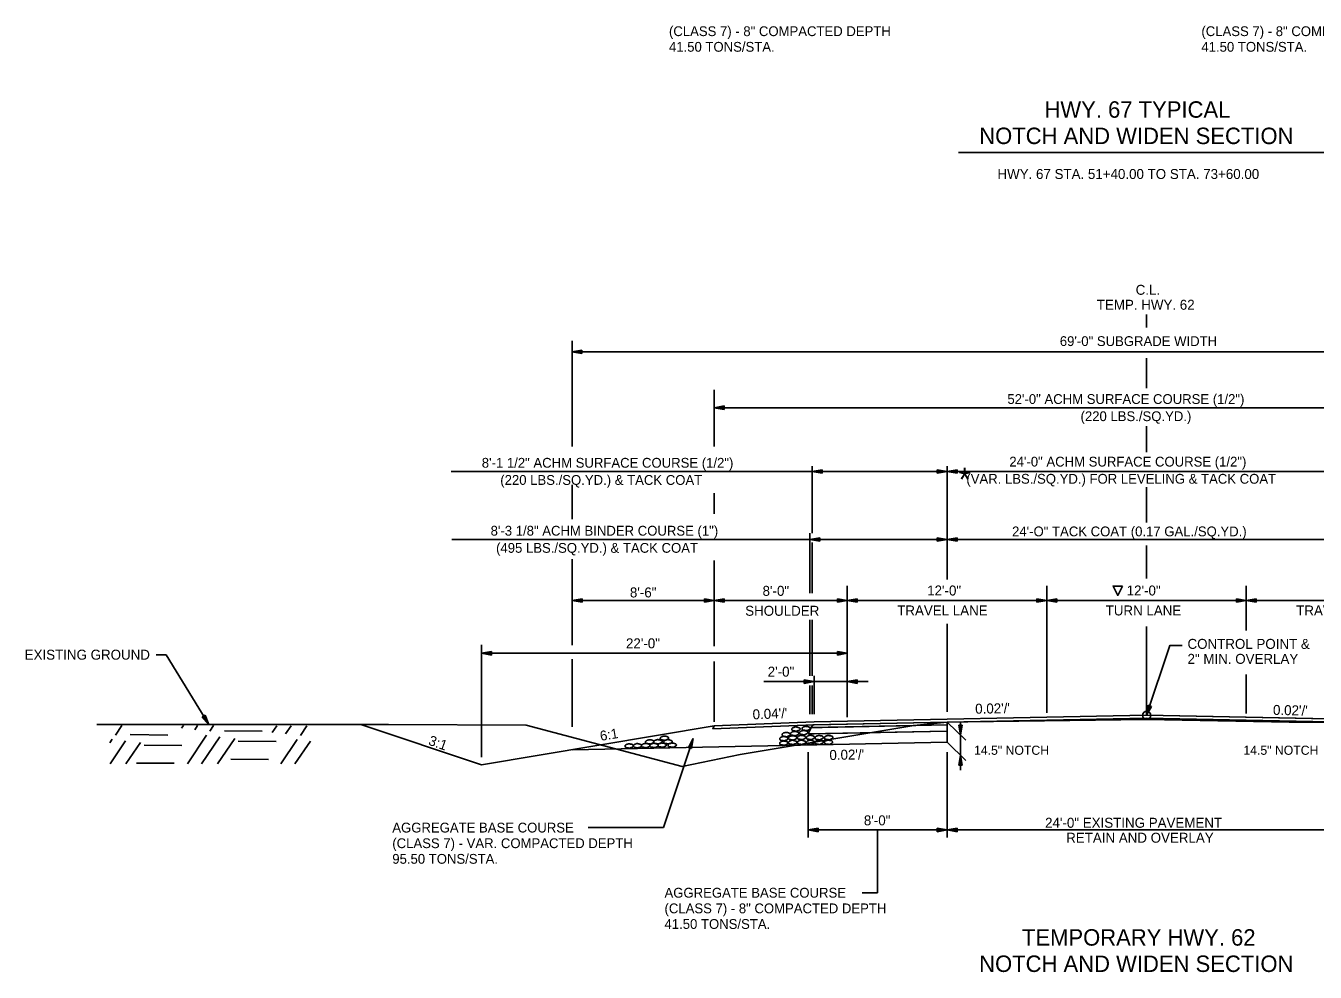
# Model space of a CAD drawing. Extents: x 1734743 to 1735935, y 759845 to 763831.
# Drawn here: x 1735682.6 to 1735760.2, y 762323.5 to 762380.5 of the extents above; entities that cross this region are included whole.
import ezdxf

# ---------------------------------------------------------------- set-up
doc = ezdxf.new("R2010")
doc.units = 0
for name, color, linetype in [('1', 7, 'Continuous'), ('10', 7, 'Continuous'), ('19', 7, 'Continuous'), ('20', 7, 'Continuous'), ('42', 7, 'Continuous'), ('Level 1', 7, 'Continuous'), ('R_Draft', 7, 'Continuous'), ('R_Prop Surface', 7, 'Continuous')]:
    doc.layers.add(name, color=color, linetype=linetype)

# ---------------------------------------------------------------- blocks, each defined once
blk = doc.blocks.new('ROCKS')
at = {"layer": '1'}
blk.add_spline([(0.013, 0.06), (0.053, 0.053), (0.107, 0.033), (0.133, 0.013), (0.133, -0.007), (0.12, -0.033), (0.107, -0.04), (0.073, -0.053), (0.033, -0.067), (0.013, -0.067), (-0.02, -0.06), (-0.06, -0.053), (-0.087, -0.047), (-0.113, -0.02), (-0.113, -0.007), (-0.107, 0.02), (-0.087, 0.033), (-0.067, 0.047), (-0.033, 0.053), (-0.02, 0.06), (0.013, 0.06)], degree=3, dxfattribs=at)

msp = doc.modelspace()

# ---------------------------------------------------------------- linework, layer by layer
at = {"layer": '1'}
msp.add_line((1735738.718, 762372.859), (1735761.293, 762372.859), dxfattribs=at)
at = {"layer": '10'}
msp.add_lwpolyline([(1735748.579, 762346.77), (1735748.298, 762346.208), (1735748.017, 762346.77)], close=True, dxfattribs=at)
at = {"layer": '19'}
for p, q in [((1735750.035, 762362.323), (1735750.035, 762363.109)), ((1735750.035, 762358.676), (1735750.035, 762360.487)), ((1735750.035, 762354.815), (1735750.035, 762356.383)), ((1735750.035, 762350.598), (1735750.035, 762352.723)), ((1735750.035, 762347.228), (1735750.035, 762349.204)), ((1735750.035, 762338.99), (1735750.035, 762344.343)), ((1735710.635, 762342.827), (1735710.035, 762342.722)), ((1735710.035, 762342.722), (1735732.035, 762342.722)), ((1735710.035, 762342.722), (1735710.635, 762342.617)), ((1735710.635, 762342.772), (1735710.195, 762342.737)), ((1735710.195, 762342.707), (1735710.635, 762342.667)), ((1735710.635, 762342.617), (1735710.635, 762342.827)), ((1735731.435, 762342.827), (1735731.435, 762342.617)), ((1735732.035, 762342.722), (1735731.435, 762342.827)), ((1735731.875, 762342.737), (1735731.435, 762342.772)), ((1735731.435, 762342.617), (1735732.035, 762342.722)), ((1735731.435, 762342.667), (1735731.875, 762342.707)), ((1735727.006, 762341.016), (1735730.035, 762341.016)), ((1735729.435, 762341.121), (1735729.435, 762340.911)), ((1735730.035, 762341.016), (1735729.435, 762341.121)), ((1735729.875, 762341.031), (1735729.435, 762341.066)), ((1735729.435, 762340.911), (1735730.035, 762341.016)), ((1735729.435, 762340.961), (1735729.875, 762341.001)), ((1735750.035, 762338.99), (1735750.127, 762339.592)), ((1735750.127, 762339.592), (1735750.325, 762339.525)), ((1735750.035, 762338.99), (1735730.035, 762338.59)), ((1735750.035, 762338.824), (1735730.035, 762338.424)), ((1735750.325, 762339.525), (1735750.035, 762338.99)), ((1735750.035, 762338.99), (1735770.04, 762338.59)), ((1735750.035, 762338.824), (1735770.04, 762338.424)), ((1735750.076, 762339.144), (1735750.176, 762339.571)), ((1735750.28, 762339.537), (1735750.1, 762339.138)), ((1735688.008, 762337.793), (1735688.401, 762338.375)), ((1735691.994, 762338.218), (1735692.101, 762338.368)), ((1735692.789, 762338.124), (1735692.955, 762338.368)), ((1735693.684, 762338.03), (1735693.911, 762338.368)), ((1735694.572, 762338.057), (1735696.832, 762338.04)), ((1735697.448, 762337.966), (1735697.711, 762338.36)), ((1735698.242, 762337.872), (1735698.575, 762338.36)), ((1735699.138, 762337.778), (1735699.52, 762338.351)), ((1735710.035, 762336.017), (1735702.77, 762338.439)), ((1735730.035, 762338.424), (1735723.95, 762338.18)), ((1735724.035, 762338.35), (1735723.95, 762338.18)), ((1735730.035, 762338.59), (1735724.035, 762338.35)), ((1735729.867, 762338.254), (1735729.677, 762337.875)), ((1735729.867, 762338.254), (1735729.677, 762337.875)), ((1735738.035, 762338.042), (1735729.677, 762337.875)), ((1735729.95, 762338.42), (1735729.867, 762338.254)), ((1735738.035, 762338.417), (1735729.867, 762338.254)), ((1735738.035, 762338.042), (1735738.034, 762338.416)), ((1735738.034, 762338.416), (1735738.034, 762338.416)), ((1735738.035, 762338.584), (1735738.035, 762337.375)), ((1735738.035, 762338.042), (1735738.035, 762338.042)), ((1735738.741, 762338.39), (1735738.951, 762338.39)), ((1735738.846, 762337.79), (1735738.741, 762338.39)), ((1735738.831, 762337.95), (1735738.791, 762338.39)), ((1735738.951, 762338.39), (1735738.846, 762337.79)), ((1735738.896, 762338.39), (1735738.861, 762337.95)), ((1735687.667, 762337.326), (1735687.822, 762337.551)), ((1735687.687, 762336.077), (1735688.616, 762337.458)), ((1735688.642, 762336.077), (1735689.511, 762337.363)), ((1735688.897, 762337.83), (1735691.156, 762337.803)), ((1735692.341, 762336.07), (1735693.498, 762337.788)), ((1735693.196, 762336.07), (1735694.292, 762337.695)), ((1735694.151, 762336.07), (1735695.187, 762337.6)), ((1735695.4, 762337.427), (1735697.671, 762337.409)), ((1735697.951, 762336.062), (1735698.951, 762337.536)), ((1735698.806, 762336.063), (1735699.746, 762337.442)), ((1735738.035, 762337.375), (1735715.478, 762336.924)), ((1735720.975, 762332.238), (1735722.76, 762337.598)), ((1735722.76, 762337.598), (1735722.472, 762337.062)), ((1735722.699, 762337.451), (1735722.523, 762337.048)), ((1735722.623, 762337.013), (1735722.725, 762337.442)), ((1735722.67, 762336.997), (1735722.76, 762337.598)), ((1735689.735, 762337.199), (1735691.995, 762337.172)), ((1735722.472, 762337.062), (1735722.67, 762336.997)), ((1735738.741, 762335.982), (1735738.846, 762336.582)), ((1735738.846, 762336.582), (1735738.951, 762335.982)), ((1735689.28, 762336.121), (1735691.55, 762336.103)), ((1735694.956, 762336.358), (1735697.215, 762336.331)), ((1735738.951, 762335.982), (1735738.741, 762335.982)), ((1735738.796, 762335.982), (1735738.831, 762336.422)), ((1735738.861, 762336.422), (1735738.901, 762335.982)), ((1735716.44, 762332.238), (1735720.975, 762332.238)), ((1735733.856, 762328.319), (1735733.856, 762332.092)), ((1735732.928, 762328.319), (1735733.856, 762328.319))]:
    msp.add_line(p, q, dxfattribs=at)
for points in [[(1735752.183, 762343.189), (1735751.428, 762343.189), (1735750.035, 762338.99)], [(1735729.677, 762337.875), (1735730.038, 762337.882), (1735738.035, 762338.042)], [(1735738.034, 762338.416), (1735730.519, 762338.267), (1735729.867, 762338.254)]]:
    msp.add_lwpolyline(points, dxfattribs=at)
for points in [[(1735770.04, 762338.59), (1735750.035, 762338.99), (1735730.035, 762338.59), (1735724.035, 762338.35), (1735723.95, 762338.18), (1735730.035, 762338.424), (1735750.035, 762338.824), (1735770.04, 762338.424), (1735776.12, 762338.18), (1735776.12, 762338.18), (1735776.035, 762338.351), (1735776.035, 762338.351)], [(1735729.95, 762338.42), (1735729.867, 762338.254), (1735738.035, 762338.417), (1735738.035, 762338.417), (1735738.035, 762338.584), (1735738.035, 762338.584)]]:
    msp.add_lwpolyline(points, close=True, dxfattribs=at)
msp.add_circle((1735750.04, 762338.988), 0.25, dxfattribs=at)
at = {"layer": '20'}
for p, q in [((1735715.478, 762361.52), (1735715.478, 762355.162)), ((1735716.073, 762360.963), (1735715.473, 762360.858)), ((1735715.473, 762360.858), (1735716.073, 762360.753)), ((1735715.478, 762360.859), (1735784.593, 762360.859)), ((1735716.073, 762360.908), (1735715.633, 762360.873)), ((1735715.633, 762360.843), (1735716.073, 762360.803)), ((1735716.073, 762360.753), (1735716.073, 762360.963)), ((1735724.035, 762355.162), (1735724.035, 762358.578)), ((1735724.63, 762357.603), (1735724.03, 762357.499)), ((1735724.03, 762357.499), (1735724.63, 762357.393)), ((1735724.035, 762357.498), (1735776.035, 762357.498)), ((1735724.63, 762357.548), (1735724.19, 762357.514)), ((1735724.19, 762357.484), (1735724.63, 762357.443)), ((1735724.63, 762357.393), (1735724.63, 762357.603)), ((1735708.21, 762353.663), (1735729.917, 762353.663)), ((1735729.917, 762349.94), (1735729.917, 762353.981)), ((1735730.517, 762353.768), (1735729.917, 762353.663)), ((1735729.917, 762353.663), (1735738.044, 762353.663)), ((1735729.917, 762353.663), (1735730.517, 762353.558)), ((1735729.917, 762353.663), (1735750.035, 762353.663)), ((1735730.517, 762353.713), (1735730.077, 762353.678)), ((1735730.077, 762353.648), (1735730.517, 762353.608)), ((1735730.517, 762353.558), (1735730.517, 762353.768)), ((1735737.442, 762353.768), (1735737.442, 762353.558)), ((1735738.042, 762353.663), (1735737.442, 762353.768)), ((1735737.882, 762353.678), (1735737.442, 762353.713)), ((1735737.442, 762353.558), (1735738.042, 762353.663)), ((1735737.442, 762353.608), (1735737.882, 762353.648)), ((1735738.042, 762347.154), (1735738.042, 762353.981)), ((1735738.042, 762353.663), (1735738.642, 762353.768)), ((1735738.642, 762353.558), (1735738.042, 762353.663)), ((1735738.202, 762353.678), (1735738.642, 762353.713)), ((1735738.642, 762353.608), (1735738.202, 762353.648)), ((1735738.642, 762353.768), (1735738.642, 762353.558)), ((1735770.153, 762353.663), (1735750.035, 762353.663)), ((1735715.478, 762352.855), (1735715.478, 762350.792)), ((1735724.035, 762351.113), (1735724.035, 762352.347)), ((1735729.782, 762346.338), (1735729.782, 762349.94)), ((1735730.382, 762349.676), (1735729.782, 762349.571)), ((1735730.382, 762349.466), (1735730.382, 762349.676)), ((1735737.442, 762349.676), (1735737.442, 762349.466)), ((1735738.042, 762349.571), (1735737.442, 762349.676)), ((1735738.042, 762349.571), (1735738.642, 762349.676)), ((1735738.642, 762349.676), (1735738.642, 762349.466)), ((1735708.241, 762349.571), (1735729.782, 762349.571)), ((1735729.782, 762349.571), (1735730.382, 762349.466)), ((1735729.782, 762349.571), (1735738.042, 762349.571)), ((1735729.917, 762346.338), (1735729.917, 762349.392)), ((1735730.382, 762349.621), (1735729.942, 762349.586)), ((1735729.942, 762349.556), (1735730.382, 762349.516)), ((1735737.882, 762349.586), (1735737.442, 762349.621)), ((1735737.442, 762349.466), (1735738.042, 762349.571)), ((1735737.442, 762349.516), (1735737.882, 762349.556)), ((1735738.042, 762349.571), (1735750.035, 762349.571)), ((1735738.642, 762349.466), (1735738.042, 762349.571)), ((1735738.202, 762349.586), (1735738.642, 762349.621)), ((1735738.642, 762349.516), (1735738.202, 762349.556)), ((1735762.028, 762349.571), (1735750.035, 762349.571)), ((1735715.478, 762348.388), (1735715.478, 762343.206)), ((1735724.035, 762343.145), (1735724.035, 762348.298)), ((1735732.035, 762338.889), (1735732.035, 762346.779)), ((1735744.035, 762339.133), (1735744.035, 762346.779)), ((1735756.035, 762344.102), (1735756.035, 762346.779)), ((1735716.078, 762346.005), (1735715.478, 762345.9)), ((1735715.478, 762345.9), (1735724.035, 762345.9)), ((1735715.478, 762345.9), (1735716.078, 762345.795)), ((1735716.078, 762345.95), (1735715.638, 762345.915)), ((1735715.638, 762345.885), (1735716.078, 762345.845)), ((1735716.078, 762345.795), (1735716.078, 762346.005)), ((1735723.435, 762346.005), (1735723.435, 762345.795)), ((1735724.035, 762345.9), (1735723.435, 762346.005)), ((1735723.875, 762345.915), (1735723.435, 762345.95)), ((1735723.435, 762345.795), (1735724.035, 762345.9)), ((1735723.435, 762345.845), (1735723.875, 762345.885)), ((1735724.635, 762346.005), (1735724.035, 762345.9)), ((1735724.035, 762345.9), (1735732.035, 762345.9)), ((1735724.035, 762345.9), (1735724.635, 762345.795)), ((1735724.635, 762345.95), (1735724.195, 762345.915)), ((1735724.195, 762345.885), (1735724.635, 762345.845)), ((1735724.635, 762345.795), (1735724.635, 762346.005)), ((1735731.435, 762346.005), (1735731.435, 762345.795)), ((1735732.035, 762345.9), (1735731.435, 762346.005)), ((1735731.875, 762345.915), (1735731.435, 762345.95)), ((1735731.435, 762345.795), (1735732.035, 762345.9)), ((1735731.435, 762345.845), (1735731.875, 762345.885)), ((1735732.635, 762346.005), (1735732.035, 762345.9)), ((1735732.035, 762345.9), (1735744.035, 762345.9)), ((1735732.035, 762345.9), (1735732.635, 762345.795)), ((1735732.635, 762345.95), (1735732.195, 762345.915)), ((1735732.195, 762345.885), (1735732.635, 762345.845)), ((1735732.635, 762345.795), (1735732.635, 762346.005)), ((1735743.435, 762346.005), (1735743.435, 762345.795)), ((1735744.035, 762345.9), (1735743.435, 762346.005)), ((1735743.875, 762345.915), (1735743.435, 762345.95)), ((1735743.435, 762345.795), (1735744.035, 762345.9)), ((1735743.435, 762345.845), (1735743.875, 762345.885)), ((1735744.035, 762345.9), (1735744.635, 762346.005)), ((1735756.035, 762345.9), (1735744.035, 762345.9)), ((1735744.635, 762345.795), (1735744.035, 762345.9)), ((1735744.195, 762345.915), (1735744.635, 762345.95)), ((1735744.635, 762345.845), (1735744.195, 762345.885)), ((1735744.635, 762346.005), (1735744.635, 762345.795)), ((1735755.435, 762345.795), (1735755.435, 762346.005)), ((1735755.435, 762346.005), (1735756.035, 762345.9)), ((1735755.435, 762345.95), (1735755.875, 762345.915)), ((1735756.035, 762345.9), (1735755.435, 762345.795)), ((1735755.875, 762345.885), (1735755.435, 762345.845)), ((1735756.035, 762345.9), (1735756.635, 762346.005)), ((1735768.035, 762345.9), (1735756.035, 762345.9)), ((1735756.635, 762345.795), (1735756.035, 762345.9)), ((1735756.195, 762345.915), (1735756.635, 762345.95)), ((1735756.635, 762345.845), (1735756.195, 762345.885)), ((1735756.635, 762346.005), (1735756.635, 762345.795)), ((1735729.782, 762341.37), (1735729.782, 762344.732)), ((1735729.917, 762341.37), (1735729.917, 762344.732)), ((1735738.042, 762339.207), (1735738.042, 762344.497)), ((1735710.035, 762336.475), (1735710.035, 762343.232)), ((1735715.478, 762342.374), (1735715.478, 762338.307)), ((1735724.035, 762338.6), (1735724.035, 762342.222)), ((1735730.035, 762339.05), (1735730.035, 762341.37)), ((1735756.035, 762339.104), (1735756.035, 762341.443)), ((1735729.782, 762339.05), (1735729.782, 762340.776)), ((1735729.917, 762339.05), (1735729.917, 762340.776)), ((1735732.035, 762341.016), (1735730.035, 762341.016)), ((1735732.035, 762341.016), (1735732.635, 762341.121)), ((1735732.635, 762340.911), (1735732.035, 762341.016)), ((1735733.29, 762341.016), (1735732.035, 762341.016)), ((1735732.195, 762341.031), (1735732.635, 762341.066)), ((1735732.635, 762340.961), (1735732.195, 762341.001)), ((1735732.635, 762341.121), (1735732.635, 762340.911)), ((1735693.413, 762339.005), (1735693.235, 762338.896)), ((1735693.235, 762338.896), (1735693.637, 762338.439)), ((1735693.276, 762338.917), (1735693.54, 762338.568)), ((1735693.563, 762338.579), (1735693.37, 762338.973)), ((1735693.637, 762338.439), (1735693.413, 762339.005)), ((1735738.035, 762338.584), (1735739.156, 762337.486)), ((1735738.035, 762337.375), (1735739.156, 762336.278)), ((1735729.677, 762331.637), (1735729.677, 762336.774)), ((1735738.035, 762331.637), (1735738.035, 762336.774)), ((1735738.035, 762334.59), (1735738.035, 762336.758)), ((1735729.677, 762332.092), (1735730.277, 762332.197)), ((1735770.398, 762332.092), (1735729.677, 762332.092)), ((1735730.277, 762331.987), (1735729.677, 762332.092)), ((1735729.837, 762332.107), (1735730.277, 762332.142)), ((1735730.277, 762332.037), (1735729.837, 762332.077)), ((1735730.277, 762332.197), (1735730.277, 762331.987)), ((1735737.435, 762331.986), (1735737.435, 762332.196)), ((1735737.435, 762332.196), (1735738.035, 762332.092)), ((1735737.435, 762332.141), (1735737.875, 762332.107)), ((1735738.035, 762332.092), (1735737.435, 762331.986)), ((1735737.875, 762332.077), (1735737.435, 762332.036)), ((1735738.035, 762332.092), (1735738.635, 762332.197)), ((1735738.635, 762331.987), (1735738.035, 762332.092)), ((1735738.195, 762332.107), (1735738.635, 762332.142)), ((1735738.635, 762332.037), (1735738.195, 762332.077)), ((1735738.635, 762332.197), (1735738.635, 762331.987))]:
    msp.add_line(p, q, dxfattribs=at)
for points in [[(1735690.454, 762342.638), (1735691.054, 762342.637), (1735693.637, 762338.439)], [(1735738.846, 762338.541), (1735738.846, 762335.689)]]:
    msp.add_lwpolyline(points, dxfattribs=at)
at = {"layer": 'R_Draft'}
for points in [[(1735722.108, 762335.919), (1735712.721, 762338.399), (1735704.444, 762338.439), (1735686.897, 762338.439)], [(1735790.168, 762331.248), (1735764.035, 762338.38), (1735762.033, 762338.584), (1735758.615, 762338.581), (1735750.035, 762338.74), (1735739.289, 762338.604), (1735738.035, 762338.584), (1735736.035, 762338.38), (1735725.594, 762336.636), (1735722.108, 762335.919)]]:
    msp.add_lwpolyline(points, dxfattribs=at)
at = {"layer": 'R_Prop Surface'}
msp.add_line((1735724.035, 762338.35), (1735710.035, 762336.017), dxfattribs=at)

# ---------------------------------------------------------------- block references
at = {"layer": 'Level 1', "xscale": 2.011654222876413}
for p, yscale, rotation in [((1735728.847, 762337.9), 2.0116542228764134, 2.041282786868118), ((1735728.925, 762338.169), 2.0116542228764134, 2.041282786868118), ((1735729.388, 762337.955), 2.0116542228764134, 2.041282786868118), ((1735729.535, 762338.204), 2.0116542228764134, 2.041282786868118), ((1735718.891, 762337.152), 2.011654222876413, 1.8263814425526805), ((1735719.391, 762337.166), 2.011654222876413, 1.8263814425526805), ((1735719.887, 762337.177), 2.011654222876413, 1.8263814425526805), ((1735720.129, 762337.399), 2.011654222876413, 1.8263814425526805), ((1735720.383, 762337.184), 2.011654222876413, 1.8263814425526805), ((1735720.622, 762337.405), 2.011654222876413, 1.8263814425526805), ((1735720.874, 762337.2), 2.011654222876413, 1.8263814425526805), ((1735721.013, 762337.62), 2.011654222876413, 1.8263814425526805), ((1735721.23, 762337.405), 2.011654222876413, 1.8263814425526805), ((1735721.482, 762337.2), 2.011654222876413, 1.8263814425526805), ((1735728.193, 762337.592), 2.0116542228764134, 2.041282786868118), ((1735728.194, 762337.322), 2.0116542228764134, 2.041282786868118), ((1735728.332, 762337.838), 2.0116542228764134, 2.041282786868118), ((1735728.726, 762337.638), 2.0116542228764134, 2.041282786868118), ((1735728.727, 762337.367), 2.0116542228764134, 2.041282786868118), ((1735729.26, 762337.663), 2.0116542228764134, 2.041282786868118), ((1735729.261, 762337.369), 2.0116542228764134, 2.041282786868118), ((1735729.795, 762337.665), 2.0116542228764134, 2.041282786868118), ((1735729.796, 762337.371), 2.0116542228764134, 2.041282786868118), ((1735730.315, 762337.373), 2.0116542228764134, 2.041282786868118), ((1735730.319, 762337.653), 2.0116542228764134, 2.041282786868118), ((1735730.885, 762337.375), 2.0116542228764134, 2.041282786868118), ((1735730.889, 762337.655), 2.0116542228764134, 2.041282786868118)]:
    msp.add_blockref('ROCKS', p, dxfattribs=dict(at, yscale=yscale, rotation=rotation))

# ---------------------------------------------------------------- texts
at = {"layer": '10'}
for s, height, rotation, p in [('HWY. 67 TYPICAL', 0.98999, 359.99538, (1735743.894, 762374.943)), ('NOTCH AND WIDEN SECTION ', 0.98999, 359.99538, (1735739.969, 762373.359)), ('HWY. 67 STA. 51+40.00 TO STA. 73+60.00', 0.6, 359.99538, (1735741.067, 762371.259)), ('*', 1.422, 359.99538, (1735738.725, 762352.47)), ('8\'-6"', 0.6, 360, (1735718.957, 762346.083)), ('TEMPORARY HWY. 62 ', 0.98999, 359.99538, (1735742.541, 762325.134)), ('NOTCH AND WIDEN SECTION', 0.98999, 359.99538, (1735739.965, 762323.55))]:
    msp.add_text(s, height=height, rotation=rotation, dxfattribs=at).set_placement(p)
for s, height, p in [('EXISTING GROUND', 0.6, (1735682.552, 762342.338)), ('14.5" NOTCH', 0.55, (1735739.657, 762336.615)), ('14.5" NOTCH', 0.55, (1735755.858, 762336.615)), ('24\'-0" EXISTING PAVEMENT', 0.6, (1735743.931, 762332.226)), ('RETAIN AND OVERLAY', 0.6, (1735745.2, 762331.326))]:
    msp.add_text(s, height=height, dxfattribs=at).set_placement(p)
at = {"layer": '19'}
for s, p in [('(CLASS 7) - 8" COMPACTED DEPTH', (1735721.307, 762379.854)), ('(CLASS 7) - 8" COMPACTED DEPTH', (1735753.333, 762379.854)), ('41.50 TONS/STA.', (1735721.307, 762378.914)), ('41.50 TONS/STA.', (1735753.333, 762378.914)), ('AGGREGATE BASE COURSE', (1735704.664, 762331.94)), ('(CLASS 7) - VAR. COMPACTED DEPTH', (1735704.664, 762331)), ('95.50 TONS/STA.', (1735704.664, 762330.06)), ('AGGREGATE BASE COURSE', (1735721.038, 762328.021)), ('(CLASS 7) - 8" COMPACTED DEPTH', (1735721.038, 762327.081)), ('41.50 TONS/STA.', (1735721.038, 762326.141))]:
    msp.add_text(s, height=0.59001, rotation=360, dxfattribs=at).set_placement(p)
at = {"layer": '42'}
for s, p in [('69\'-0" SUBGRADE WIDTH', (1735744.816, 762361.208)), ('52\'-0" ACHM SURFACE COURSE (1/2")', (1735741.663, 762357.723)), ('(220 LBS./SQ.YD.)', (1735746.063, 762356.69)), ('8\'-1 1/2" ACHM SURFACE COURSE (1/2")', (1735710.047, 762353.888)), ('24\'-0" ACHM SURFACE COURSE (1/2")', (1735741.781, 762353.957)), (' (VAR. LBS./SQ.YD.) FOR LEVELING & TACK COAT', (1735738.975, 762352.925)), ('(220 LBS./SQ.YD.) & TACK COAT', (1735711.16, 762352.855)), ('8\'-3 1/8" ACHM BINDER COURSE (1")', (1735710.579, 762349.801)), ('24\'-O" TACK COAT (0.17 GAL./SQ.YD.)', (1735741.945, 762349.76)), ('(495 LBS./SQ.YD.) & TACK COAT', (1735710.907, 762348.769))]:
    msp.add_text(s, height=0.59001, rotation=360, dxfattribs=at).set_placement(p)
at = {"layer": 'R_Draft'}
for s, p in [('C.L.', (1735749.38, 762364.29)), ('TEMP. HWY. 62', (1735747.041, 762363.39)), ('8\'-0"', (1735726.937, 762346.179)), ('12\'-0"', (1735736.837, 762346.2)), ('12\'-0"', (1735748.837, 762346.2)), ('SHOULDER', (1735725.892, 762344.979)), ('TRAVEL LANE', (1735735.035, 762345)), ('TURN LANE', (1735747.574, 762345)), ('TRAVEL LANE', (1735759.035, 762345)), ('22\'-0"', (1735718.72, 762343.022)), ('CONTROL POINT &', (1735752.498, 762342.988)), ('2" MIN. OVERLAY', (1735752.498, 762342.088)), ('2\'-0"', (1735727.245, 762341.319)), ('8\'-0"', (1735733.031, 762332.371))]:
    msp.add_text(s, height=0.6, dxfattribs=at).set_placement(p)
for s, height, rotation, p in [("0.02'/'", 0.6, 1.14576, (1735739.732, 762339.084)), ("0.02'/'", 0.6, 358.85424, (1735757.635, 762339.018)), ("0.04'/'", 0.6, 2.29061, (1735726.35, 762338.744)), ('6:1', 0.59, 9.46232, (1735717.207, 762337.449)), ('3:1', 0.6, 340.49426, (1735706.792, 762337.233)), ("0.02'/'", 0.6, 1.14576, (1735730.964, 762336.302))]:
    msp.add_text(s, height=height, rotation=rotation, dxfattribs=at).set_placement(p)

doc.saveas('drawing.dxf')
